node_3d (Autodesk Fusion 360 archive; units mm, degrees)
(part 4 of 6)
derived_instance "DerivedInstance2"
derived_instance "DerivedInstance3"
derived_instance "DerivedInstance4"
derived_instance "DerivedInstance5"
derived_instance "DerivedInstance6"
derived_instance "DerivedInstance7"
derived_instance "DerivedInstance8"
derived_instance "DerivedInstance9"
derived_instance "DerivedInstance10"
derived_instance "DerivedInstance11"
derived_instance "DerivedInstance12"
derived_instance "DerivedInstance1"
derived_instance "DerivedInstance1"
derived_instance "DerivedInstance2"
derived_instance "DerivedInstance3"
derived_instance "DerivedInstance4"
component_insert "Component Insert"
sketch "base" plane through (0, 0, 0) normal (0, 0, 1) x axis (1, 0, 0)
  line L1 (-159.967, -29.782) -> (-254.967, -29.718)
  line L2 (-156.0303, -123.7846) -> (-155.9697, -33.7847)
  line L3 (-255.033, -127.718) -> (-160.033, -127.782)
  line L4 (-258.9697, -33.7154) -> (-259.0303, -123.7153)
  line L5 (-259, -78.7153) -> (-156, -78.7847)
  line L6 (-207.533, -127.75) -> (-207.467, -29.75)
  line L7 (-255, -25.25) -> (-160, -25.25)
  line L8 (-261, -126.25) -> (-261, -31.25)
  line L9 (-160, -132.25) -> (-255, -132.25)
  line L10 (-154, -31.25) -> (-154, -126.25)
  line L11 (-261, -132.25) -> (-154, -25.25)
  line L12 (-154, -132.25) -> (-261, -25.25)
  line L13 (-159.9667, -29.282) -> (-254.9667, -29.218)
  line L14 (-259.4697, -33.715) -> (-259.5303, -123.715)
  line L15 (-255.0333, -128.218) -> (-160.0333, -128.282)
  line L16 (-155.5303, -123.785) -> (-155.4697, -33.785)
  line L17 (-255, -27.25) -> (-160, -27.25)
  line L18 (-259, -126.25) -> (-259, -31.25)
  line L19 (-160, -130.25) -> (-255, -130.25)
  line L20 (-156, -31.25) -> (-156, -126.25)
  arc A1 centre (-254.9697, -33.718) radius 4 clockwise from (-258.9697, -33.7154) to (-254.967, -29.718)
  arc A2 centre (-159.9697, -33.782) radius 4 clockwise from (-159.967, -29.782) to (-155.9697, -33.7847)
  arc A3 centre (-160.0303, -123.782) radius 4 clockwise from (-156.0303, -123.7846) to (-160.033, -127.782)
  arc A4 centre (-255.0303, -123.718) radius 4 clockwise from (-255.033, -127.718) to (-259.0303, -123.7153)
  arc A5 centre (-159.9697, -33.782) radius 4.5 clockwise from (-159.9667, -29.282) to (-155.4697, -33.785)
  arc A6 centre (-254.9697, -33.718) radius 4.5 clockwise from (-259.4697, -33.715) to (-254.9667, -29.218)
  arc A7 centre (-255.0303, -123.718) radius 4.5 clockwise from (-255.0333, -128.218) to (-259.5303, -123.715)
  arc A8 centre (-160.0303, -123.782) radius 4.5 clockwise from (-155.5303, -123.785) to (-160.0333, -128.282)
  arc A9 centre (-255, -126.25) radius 6 clockwise from (-255, -132.25) to (-261, -126.25)
  arc A10 centre (-160, -126.25) radius 6 clockwise from (-154, -126.25) to (-160, -132.25)
  arc A11 centre (-160, -31.25) radius 6 clockwise from (-160, -25.25) to (-154, -31.25)
  arc A12 centre (-255, -31.25) radius 6 clockwise from (-261, -31.25) to (-255, -25.25)
  arc A13 centre (-255, -31.25) radius 4 clockwise from (-259, -31.25) to (-255, -27.25)
  arc A14 centre (-255, -126.25) radius 4 clockwise from (-255, -130.25) to (-259, -126.25)
  arc A15 centre (-160, -126.25) radius 4 clockwise from (-156, -126.25) to (-160, -130.25)
  arc A16 centre (-160, -31.25) radius 4 clockwise from (-160, -27.25) to (-156, -31.25)
  point P2 (-258.967, -29.7154)
  point P3 (-155.967, -29.7847)
  point P4 (-259.033, -127.7153)
  point P17 (-156, -78.7847)
  point P18 (-259, -78.7153)
  point P19 (-207.467, -29.75)
  point P20 (-207.533, -127.75)
  point P25 (-207.5, -78.75)
  point P23 (-261, -132.25)
  point P24 (-154, -132.25)
  point P21 (-154, -25.25)
  point P22 (-261, -25.25)
  coincident P2 L1
  coincident P2 L4
  tangent L1 A1
  tangent L4 A1
  coincident P3 L2
  coincident P3 L1
  tangent L2 A2
  tangent L1 A2
  equal A1 A2
  tangent L3 A3
  tangent L2 A3
  equal A1 A3
  coincident P4 L3
  coincident P4 L4
  tangent L3 A4
  tangent L4 A4
  equal A1 A4
  midpoint L2 P17
  midpoint L4 P18
  midpoint L1 P19
  midpoint L3 P20
  perpendicular L3 L6
  horizontal L7
  perpendicular L7 L8
  parallel L7 L9
  parallel L8 L10
  coincident L11 P25
  coincident L12 P25
  midpoint L6 P25
  coincident P23 L9
  coincident P23 L8
  tangent L9 A9
  tangent L8 A9
  coincident P24 L9
  coincident P24 L10
  tangent L9 A10
  tangent L10 A10
  equal A9 A10
  coincident P21 L10
  coincident P21 L7
  tangent L10 A11
  tangent L7 A11
  equal A9 A11
  coincident P22 L7
  coincident P22 L8
  tangent L7 A12
  tangent L8 A12
  equal A9 A12
  dimension "d3" radius A1 = 4
  dimension "d4" distance L1 L3 = 98
  dimension "d5" distance L2 L4 = 103
  dimension "d6" distance P23 P24 = 107
  dimension "d7" distance P22 P23 = 107
  dimension "d8_1" = -0.5
  dimension "d9_1" = -2
  dimension "d15" radius A9 = 6
extrude "Extrude1" new body sketch "base" profile of L1 L2 L3 L4 A1 A2 A3 A4 L5 L6 L7 L8 L9 L10 L13 L16 A8 L14 A5 A7 L15 A6 L20 L17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 against normal blind 25
shell "Shell1" innerThickness 2
fillet "Fillet1" radius 5
sketch "Sketch5" plane through (0, 0, 0) normal (0, 0, 1) x axis (1, 0, 0)
  line L1 (-240.7563, -46.258) -> (-242.2295, -46.258)
  line L2 (-240.7563, -45.242) -> (-240.7563, -46.258)
  line L3 (-242.2295, -45.242) -> (-240.7563, -45.242)
  line L4 (-242.2295, -44.3328) -> (-242.2295, -45.242)
  line L5 (-242.6105, -44.3328) -> (-242.2295, -44.3328)
  line L6 (-242.6105, -45.242) -> (-242.6105, -44.3328)
  line L7 (-244.0837, -45.242) -> (-242.6105, -45.242)
  line L8 (-244.0837, -46.258) -> (-244.0837, -45.242)
  line L9 (-242.6105, -46.258) -> (-244.0837, -46.258)
  line L10 (-242.6105, -47.1672) -> (-242.6105, -46.258)
  line L11 (-242.2295, -47.1672) -> (-242.6105, -47.1672)
  line L12 (-242.2295, -46.258) -> (-242.2295, -47.1672)
  line L13 (-241, -45.75) -> (-240.7563, -45.75)
  line L14 (-244.0837, -45.75) -> (-241, -45.75)
  line L15 (-242.42, -47.1672) -> (-242.42, -44.3328)
  line L16 (-34.62, 33.38) -> (-34.62, 31.88)
  line L17 (-33.38, 31.88) -> (-34.62, 31.88)
  line L18 (-33.38, 31.9) -> (-33.38, 31.88)
  line L19 (-33.38, 33.38) -> (-33.38, 31.9)
  line L20 (-33.38, 33.38) -> (-31.88, 33.38)
  line L21 (-31.88, 33.38) -> (-31.88, 34.62)
  line L22 (-33.38, 34.62) -> (-31.88, 34.62)
  line L23 (-33.38, 34.62) -> (-33.38, 36.12)
  line L24 (-33.38, 36.12) -> (-34.62, 36.12)
  line L25 (-34.62, 34.62) -> (-34.62, 36.12)
  line L26 (-34.62, 34.62) -> (-36.12, 34.62)
  line L27 (-36.12, 33.38) -> (-36.12, 34.62)
  line L28 (-34.62, 33.38) -> (-36.12, 33.38)
  line L29 (-243.04, -46.37) -> (-243.04, -47.75)
  line L30 (-241.8, -47.75) -> (-243.04, -47.75)
  line L31 (-241.8, -47.85) -> (-241.8, -47.75)
  line L32 (-241.8, -46.37) -> (-241.8, -47.85)
  line L33 (-241.8, -46.37) -> (-240.3, -46.37)
  line L34 (-240.3, -46.37) -> (-240.3, -45.13)
  line L35 (-241.8, -45.13) -> (-240.3, -45.13)
  line L36 (-241.8, -45.13) -> (-241.8, -43.75)
  line L37 (-241.8, -43.75) -> (-243.04, -43.75)
  line L38 (-243.04, -45.13) -> (-243.04, -43.75)
  line L39 (-243.04, -45.13) -> (-244.54, -45.13)
  line L40 (-244.54, -46.37) -> (-244.54, -45.13)
  line L41 (-243.04, -46.37) -> (-244.54, -46.37)
  circle C1 centre (-34, 34) radius 2.75
  circle C2 centre (-242.42, -45.75) radius 2.75
  point P14 (-240.7563, -45.75)
  point P16 (-244.0837, -45.75)
  point P17 (-242.42, -44.3328)
  point P18 (-242.42, -47.1672)
  point P33 (-242.42, -45.75)
  point P29 (-33.38, 36.12)
  point P31 (-34.62, 36.12)
  point P22 (-36.12, 34.62)
  point P24 (-36.12, 33.38)
  point P44 (-241.8, -43.75)
  point P46 (-243.04, -43.75)
  point P37 (-244.54, -45.13)
  point P39 (-244.54, -46.37)
  point P42 (-242.42, -45.75)
  midpoint L2 P14
  perpendicular L2 L13
  midpoint L8 P16
  midpoint L5 P17
  midpoint L11 P18
  horizontal L24
  vertical L27
  perpendicular L26 L27
  perpendicular L27 L28
  perpendicular L16 L28
  perpendicular L20 L21
  perpendicular L25 L26
  perpendicular L22 L23
  perpendicular L17 L18
  perpendicular L17 L19
  midpoint L15 P33
  horizontal L37
  vertical L40
  perpendicular L39 L40
  perpendicular L40 L41
  perpendicular L29 L41
  perpendicular L33 L34
  perpendicular L38 L39
  perpendicular L35 L36
  perpendicular L30 L31
  perpendicular L30 L32
  dimension "d16_1" distance P29 P31 = 1.24
  dimension "d17_1" distance P22 P24 = 1.24
  dimension "d18_1" diameter C1 = 5.5
  dimension "d19_1" distance P44 P46 = 1.24
  dimension "d20_1" distance P37 P39 = 1.24
  dimension "d21_1" diameter C2 = 5.5
  dimension "d22_1" distance P42 L37 = 2
  dimension "d23_1" distance P42 L30 = 2
  dimension "d24_1" distance P42 L40 = 2.12
  dimension "d25_1" distance P33 L34 = 2.12
sketch "flat" plane through (0, 0, 0) normal (0, 0, 1) x axis (1, 0, 0)
  line L1 (-159.5, -30.25) -> (-254.5, -30.25)
  line L2 (-254.5, -128.25) -> (-159.5, -128.25)
  line L3 (-207, -128.25) -> (-207, -30.25)
  line L4 (-155.5, -79.25) -> (-258.5, -79.25)
  line L5 (-258.5, -27.75) -> (-155.5, -130.75)
  line L6 (-155.5, -27.75) -> (-258.5, -130.75)
  line L7 (-250.4, -129.15) -> (-163.6, -129.15)
  line L8 (-256.9, -35.85) -> (-256.9, -122.65)
  line L9 (-163.6, -29.35) -> (-250.4, -29.35)
  line L10 (-157.1, -122.65) -> (-157.1, -35.85)
  line L11 (-192, -27.75) -> (-222, -27.75)
  line L12 (-196.59, -130.75) -> (-163.6, -130.75)
  line L13 (-155.5, -122.65) -> (-155.5, -35.85)
  line L14 (-163.6, -27.75) -> (-250.4, -27.75)
  line L15 (-258.5, -35.85) -> (-258.5, -122.65)
  line L16 (-217, -130.75) -> (-197, -130.75)
  line L17 (-217, -129.15) -> (-217, -130.34)
  line L18 (-197, -129.15) -> (-217, -129.15)
  line L19 (-197, -130.34) -> (-197, -129.15)
  line L20 (-217.41, -130.75) -> (-250.4, -130.75)
  line L21 (-155.5, -89.25) -> (-155.5, -69.25)
  line L22 (-155.91, -69.25) -> (-157.1, -69.25)
  line L23 (-157.1, -69.25) -> (-157.1, -89.25)
  line L24 (-157.1, -89.25) -> (-155.91, -89.25)
  line L25 (-197, -27.75) -> (-217, -27.75)
  line L26 (-217, -28.16) -> (-217, -29.35)
  line L27 (-217, -29.35) -> (-197, -29.35)
  line L28 (-197, -29.35) -> (-197, -28.16)
  line L29 (-258.5, -69.25) -> (-258.5, -89.25)
  line L30 (-258.09, -89.25) -> (-256.9, -89.25)
  line L31 (-256.9, -89.25) -> (-256.9, -69.25)
  line L32 (-256.9, -69.25) -> (-258.09, -69.25)
  line L33 (-217.41, -130.75) -> (-196.59, -130.75)
  arc A1 centre (-254.5, -34.25) radius 4 clockwise from (-258.5, -34.25) to (-254.5, -30.25)
  arc A2 centre (-159.5, -34.25) radius 4 clockwise from (-159.5, -30.25) to (-155.5, -34.25)
  arc A3 centre (-159.5, -124.25) radius 4 clockwise from (-155.5, -124.25) to (-159.5, -128.25)
  arc A4 centre (-254.5, -124.25) radius 4 clockwise from (-254.5, -128.25) to (-258.5, -124.25)
  arc A5 centre (-163.6, -122.65) radius 6.5 clockwise from (-157.1, -122.65) to (-163.6, -129.15)
  arc A6 centre (-250.4, -122.65) radius 6.5 clockwise from (-250.4, -129.15) to (-256.9, -122.65)
  arc A7 centre (-250.4, -35.85) radius 6.5 clockwise from (-256.9, -35.85) to (-250.4, -29.35)
  arc A8 centre (-163.6, -35.85) radius 6.5 clockwise from (-163.6, -29.35) to (-157.1, -35.85)
  arc A9 centre (-250.4, -122.65) radius 8.1 clockwise from (-250.4, -130.75) to (-258.5, -122.65)
  arc A10 centre (-163.6, -122.65) radius 8.1 clockwise from (-155.5, -122.65) to (-163.6, -130.75)
  arc A11 centre (-163.6, -35.85) radius 8.1 clockwise from (-163.6, -27.75) to (-155.5, -35.85)
  arc A12 centre (-250.4, -35.85) radius 8.1 clockwise from (-258.5, -35.85) to (-250.4, -27.75)
  arc A13 centre (-196.59, -130.34) radius 0.41 clockwise from (-196.59, -130.75) to (-197, -130.34)
  arc A14 centre (-217.41, -130.34) radius 0.41 clockwise from (-217, -130.34) to (-217.41, -130.75)
  arc A15 centre (-155.91, -68.84) radius 0.41 clockwise from (-155.5, -68.84) to (-155.91, -69.25)
  arc A16 centre (-155.91, -89.66) radius 0.41 clockwise from (-155.91, -89.25) to (-155.5, -89.66)
  arc A17 centre (-217.41, -28.16) radius 0.41 clockwise from (-217.41, -27.75) to (-217, -28.16)
  arc A18 centre (-196.59, -28.16) radius 0.41 clockwise from (-197, -28.16) to (-196.59, -27.75)
  arc A19 centre (-258.09, -89.66) radius 0.41 clockwise from (-258.5, -89.66) to (-258.09, -89.25)
  arc A20 centre (-258.09, -68.84) radius 0.41 clockwise from (-258.09, -69.25) to (-258.5, -68.84)
  point P13 (-207, -79.25)
  point P5 (-207, -30.25)
  point P2 (-258.5, -30.25)
  point P3 (-155.5, -30.25)
  point P6 (-207, -128.25)
  point P4 (-258.5, -128.25)
  point P52 (-197, -130.75)
  point P53 (-217, -130.75)
  point P11 (-258.5, -27.75)
  point P12 (-155.5, -27.75)
  point P10 (-258.5, -130.75)
  point P26 (-222, -27.75)
  point P27 (-192, -27.75)
  point P55 (-197, -129.15)
  coincident L5 P13
  coincident L6 P13
  midpoint L4 P13
  coincident L1 P5
  coincident P2 L1
  tangent L1 A1
  coincident P3 L1
  tangent L1 A2
  coincident L2 P6
  tangent L2 A3
  equal A2 A3
  coincident P4 L2
  tangent L2 A4
  equal A2 A4
  horizontal L11
  tangent L7 A5
  tangent L10 A5
  tangent L7 A6
  tangent L8 A6
  tangent L8 A7
  tangent L9 A7
  equal A6 A7
  tangent L9 A8
  tangent L10 A8
  equal A6 A8
  horizontal L16
  vertical L17
  horizontal L18
  vertical L19
  concentric A6 A9
  concentric A5 A10
  concentric A8 A11
  concentric A7 A12
  tangent A9 L15
  tangent L14 A12
  tangent L13 A11
  tangent A9 L12
  tangent A10 L13
  tangent L12 A10
  tangent A11 L14
  tangent A12 L15
  coincident L12 L16
  coincident P52 L19
  tangent L12 A13
  tangent L19 A13
  tangent A9 L20
  coincident P53 L20
  coincident P53 L17
  tangent L20 A14
  tangent L17 A14
  dimension "d26_1" distance P2 P3 = 103
  dimension "d27_1" distance P2 P4 = 98
  dimension "d28_1" distance P11 P12 = 103
  dimension "d29_1" distance P10 P11 = 103
  dimension "d30_1" radius A1 = 4
  dimension "d31" radius A2 = 4
  dimension "d35_1" distance P26 P27 = 30
  dimension "d47" radius A5 = 6.5
  dimension "d48" radius A6 = 6.5
  dimension "d59" distance P52 P53 = 20
  dimension "d60" distance P52 P55 = 1.6
  dimension "d61" radius A13 = 0.41
  dimension "d62" radius A14 = 0.41
  dimension "d64" C-Pattern1-Angle = 360
extrude "Extrude2" new body sketch "flat" profile of L7 L10 L9 L8 A5 A6 A7 A8 along normal blind 1.6
sketch "perp" plane through (0, 0, 0) normal (0, 1, 0) x axis (1, 0, 0)
  line L1 (-196.59, 0) -> (-163.6, 0)
  line L2 (-196.59, -1.6) -> (-196.59, 0)
  line L3 (-163.6, -1.6) -> (-196.59, -1.6)
  line L4 (-163.6, 0) -> (-163.6, -1.6)
  line L5 (-196.59, 0) -> (-197, 0)
  line L6 (-197, -1.6) -> (-197, 0)
  line L7 (-196.59, -1.6) -> (-197, -1.6)
  line L8 (-196.59, 0) -> (-196.59, -1.6)
  line L9 (-217, 0) -> (-197, 0)
  line L10 (-217, -1.6) -> (-217, 0)
  line L11 (-197, -1.6) -> (-217, -1.6)
  line L12 (-197, 0) -> (-197, -1.6)
  line L13 (-250.4, 0) -> (-217.41, 0)
  line L14 (-250.4, -1.6) -> (-250.4, 0)
  line L15 (-217.41, -1.6) -> (-250.4, -1.6)
  line L16 (-217.41, 0) -> (-217.41, -1.6)
  line L17 (-217, 0) -> (-217.41, 0)
  line L18 (-217.41, -1.6) -> (-217.41, 0)
  line L19 (-217, -1.6) -> (-217.41, -1.6)
  line L20 (-217, 0) -> (-217, -1.6)
  line L21 (-207, 0) -> (-207, -1.6)
  line L22 (-217, -0.8) -> (-197, -0.8)
  line L23 (-196, 4.2) -> (-218, 4.2)
  line L24 (-193, -2.8) -> (-193, 1.2)
  line L25 (-218, -5.8) -> (-196, -5.8)
  line L26 (-221, 1.2) -> (-221, -2.8)
  line L27 (-193, -5.8) -> (-221, 4.2)
  line L28 (-221, -5.8) -> (-193, 4.2)
  line L29 (-217, -1.6) -> (-221, -1.6)
  line L30 (-217, 0) -> (-217, -1.6)
  line L31 (-221, 0) -> (-217, 0)
  line L32 (-221, -1.6) -> (-221, 0)
  line L33 (-221.2, 0.2) -> (-216.8, 0.2)
  line L34 (-221.2, -1.8) -> (-221.2, 0.2)
  line L35 (-216.8, -1.8) -> (-221.2, -1.8)
  line L36 (-216.8, 0.2) -> (-216.8, -1.8)
  line L37 (-197.2, -1.8) -> (-192.8, -1.8)
  line L38 (-197.2, 0.2) -> (-197.2, -1.8)
  line L39 (-192.8, -1.8) -> (-192.8, 0.2)
  line L40 (-192.8, 0.2) -> (-197.2, 0.2)
  line L41 (-207.85, -3.24) -> (-207.85, 1.64)
  line L42 (-206.15, 1.64) -> (-206.15, -3.24)
  line L43 (-207.85, -4.09) -> (-206.15, 2.49)
  line L44 (-206.15, -4.09) -> (-207.85, 2.49)
  line L45 (-208.69, 1.64) -> (-208.69, -3.24)
  line L46 (-210.39, -3.24) -> (-210.39, 1.64)
  line L47 (-211.23, 1.64) -> (-211.23, -3.24)
  line L48 (-212.93, -3.24) -> (-212.93, 1.64)
  line L49 (-203.61, 1.64) -> (-203.61, -3.24)
  line L50 (-205.31, -3.24) -> (-205.31, 1.64)
  line L51 (-201.07, 1.64) -> (-201.07, -3.24)
  line L52 (-202.77, -3.24) -> (-202.77, 1.64)
  arc A1 centre (-196, -2.8) radius 3 clockwise from (-193, -2.8) to (-196, -5.8)
  arc A2 centre (-196, 1.2) radius 3 clockwise from (-196, 4.2) to (-193, 1.2)
  arc A3 centre (-218, 1.2) radius 3 clockwise from (-221, 1.2) to (-218, 4.2)
  arc A4 centre (-218, -2.8) radius 3 clockwise from (-218, -5.8) to (-221, -2.8)
  arc A5 centre (-207, -3.24) radius 0.85 clockwise from (-207, -4.09) to (-207.85, -3.24)
  arc A6 centre (-207, -3.24) radius 0.85 clockwise from (-206.15, -3.24) to (-207, -4.09)
  arc A7 centre (-207, 1.64) radius 0.85 clockwise from (-207.85, 1.64) to (-207, 2.49)
  arc A8 centre (-207, 1.64) radius 0.85 clockwise from (-207, 2.49) to (-206.15, 1.64)
  arc A9 centre (-209.54, -3.24) radius 0.85 clockwise from (-208.69, -3.24) to (-209.54, -4.09)
  arc A10 centre (-209.54, 1.64) radius 0.85 clockwise from (-209.54, 2.49) to (-208.69, 1.64)
  arc A11 centre (-209.54, -3.24) radius 0.85 clockwise from (-209.54, -4.09) to (-210.39, -3.24)
  arc A12 centre (-209.54, 1.64) radius 0.85 clockwise from (-210.39, 1.64) to (-209.54, 2.49)
  arc A13 centre (-212.08, -3.24) radius 0.85 clockwise from (-211.23, -3.24) to (-212.08, -4.09)
  arc A14 centre (-212.08, 1.64) radius 0.85 clockwise from (-212.08, 2.49) to (-211.23, 1.64)
  arc A15 centre (-212.08, -3.24) radius 0.85 clockwise from (-212.08, -4.09) to (-212.93, -3.24)
  arc A16 centre (-212.08, 1.64) radius 0.85 clockwise from (-212.93, 1.64) to (-212.08, 2.49)
  arc A17 centre (-204.46, -3.24) radius 0.85 clockwise from (-203.61, -3.24) to (-204.46, -4.09)
  arc A18 centre (-204.46, 1.64) radius 0.85 clockwise from (-204.46, 2.49) to (-203.61, 1.64)
  arc A19 centre (-204.46, -3.24) radius 0.85 clockwise from (-204.46, -4.09) to (-205.31, -3.24)
  arc A20 centre (-204.46, 1.64) radius 0.85 clockwise from (-205.31, 1.64) to (-204.46, 2.49)
  arc A21 centre (-201.92, -3.24) radius 0.85 clockwise from (-201.07, -3.24) to (-201.92, -4.09)
  arc A22 centre (-201.92, 1.64) radius 0.85 clockwise from (-201.92, 2.49) to (-201.07, 1.64)
  arc A23 centre (-201.92, -3.24) radius 0.85 clockwise from (-201.92, -4.09) to (-202.77, -3.24)
  arc A24 centre (-201.92, 1.64) radius 0.85 clockwise from (-202.77, 1.64) to (-201.92, 2.49)
  circle C1 centre (-207, -0.8) radius 0.5
  circle C2 centre (-204.46, -0.8) radius 0.5
  circle C3 centre (-201.92, -0.8) radius 0.5
  circle C4 centre (-209.54, -0.8) radius 0.5
  circle C5 centre (-212.08, -0.8) radius 0.5
  point P22 (-207, -1.6)
  point P23 (-207, 0)
  point P24 (-197, -0.8)
  point P25 (-217, -0.8)
  point P30 (-207, -0.8)
  point P11 (-217, 0)
  point P33 (-217, 0)
  point P31 (-221, -1.6)
  point P35 (-216.8, 0.2)
  point P41 (-197.2, 0.2)
  point P36 (-221.2, 0.2)
  point P42 (-192.8, 0.2)
  point P37 (-221.2, -1.8)
  point P39 (-192.8, -1.8)
  point P38 (-216.8, -1.8)
  point P40 (-197.2, -1.8)
  point P28 (-193, -5.8)
  point P27 (-193, 4.2)
  point P26 (-221, 4.2)
  point P29 (-221, -5.8)
  point P59 (-207, -0.8)
  point P57 (-207.85, -4.09)
  point P58 (-206.15, -4.09)
  point P60 (-207, -4.09)
  point P63 (-207, -4.09)
  point P56 (-207.85, 2.49)
  point P55 (-206.15, 2.49)
  point P67 (-207, 2.49)
  point P70 (-207, 2.49)
  point P120 (-207, -0.8)
  midpoint L11 P22
  midpoint L9 P23
  midpoint L12 P24
  midpoint L20 P25
  horizontal L23
  perpendicular L23 L24
  parallel L23 L25
  parallel L24 L26
  coincident L27 P30
  coincident L28 P30
  midpoint L22 P30
  horizontal L29
  vertical L30
  horizontal L31
  vertical L32
  coincident P11 P33
  coincident L26 P31
  coincident L15 P31
  symmetric L21 P35 P41
  symmetric L21 P36 P42
  symmetric L21 P37 P39
  symmetric L21 P38 P40
  coincident P28 L25
  coincident P28 L24
  tangent L25 A1
  tangent L24 A1
  coincident P27 L24
  coincident P27 L23
  tangent L24 A2
  tangent L23 A2
  equal A1 A2
  coincident P26 L23
  coincident P26 L26
  tangent L23 A3
  tangent L26 A3
  equal A1 A3
  coincident P29 L26
  coincident P29 L25
  tangent L26 A4
  tangent L25 A4
  equal A1 A4
  parallel L41 L42
  coincident L43 P59
  coincident L44 P59
  coincident P30 P59
  coincident P57 L41
  tangent L41 A5
  coincident P58 L42
  tangent L42 A6
  coincident P60 P63
  coincident P56 L41
  tangent L41 A7
  equal A6 A7
  coincident P55 L42
  tangent L42 A8
  equal A6 A8
  coincident P67 P70
  coincident P59 P120
  dimension "d65" distance P28 P29 = 28
  dimension "d66" distance P27 P28 = 10
  dimension "d67" = 0.2
  dimension "d71" radius A1 = 3
  dimension "d92" distance P57 P58 = 1.7
  dimension "d93" distance P56 P57 = 6.58
  dimension "d94" radius A5 = 0.85
  dimension "d95" radius A6 = 0.85
  dimension "d109" diameter C1 = 1
  dimension "d98" R-Pattern1-uDistance = -2.54
  dimension "d99" R-Pattern1-vDistance = 0
  dimension "d102" R-Pattern2-uDistance = 2.54
  dimension "d103" R-Pattern2-vDistance = 0
  dimension "d112" R-Pattern3-uDistance = 2.54
  dimension "d113" R-Pattern3-vDistance = 0
  dimension "d116" R-Pattern4-uDistance = -2.54
  dimension "d117" R-Pattern4-vDistance = 0
extrude "Extrude3" sketch "perp" profile of L9 L11 L23 L24 L25 L26 L36 L33 L35 L37 L38 L40 A1 A2 A3 A4 L41 L42 A5 A6 A7 A8 A9 L45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 blind 1.6
extrude "Extrude4" sketch "perp" profile of L9 L11 L23 L24 L25 L26 L36 L33 L35 L37 L38 L40 A1 A2 A3 A4 L41 L42 A5 A6 A7 A8 A9 L45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 blind -1.6
component_from_bodies "Body->Comp1"
component_from_bodies "Body->Comp2"
sketch "body" plane through (0, 0, 0) normal (0, 0, 1) x axis (1, 0, 0)
  line L1 (-157.1, -69.25) -> (-157.1, -89.25)
  line L2 (-155.91, -69.25) -> (-157.1, -69.25)
  line L3 (-155.5, -35.85) -> (-155.5, -68.84)
  line L4 (-196.59, -27.75) -> (-163.6, -27.75)
  line L5 (-197, -29.35) -> (-197, -28.16)
  line L6 (-217, -29.35) -> (-197, -29.35)
  line L7 (-217, -28.16) -> (-217, -29.35)
  line L8 (-250.4, -27.75) -> (-217.41, -27.75)
  line L9 (-258.5, -68.84) -> (-258.5, -35.85)
  line L10 (-256.9, -69.25) -> (-258.09, -69.25)
  line L11 (-256.9, -89.25) -> (-256.9, -69.25)
  line L12 (-258.09, -89.25) -> (-256.9, -89.25)
  line L13 (-258.5, -122.65) -> (-258.5, -89.66)
  line L14 (-217.41, -130.75) -> (-250.4, -130.75)
  line L15 (-217, -129.15) -> (-217, -130.34)
  line L16 (-197, -129.15) -> (-217, -129.15)
  line L17 (-197, -130.34) -> (-197, -129.15)
  line L18 (-163.6, -130.75) -> (-196.59, -130.75)
  line L19 (-155.5, -89.66) -> (-155.5, -122.65)
  line L20 (-157.1, -89.25) -> (-155.91, -89.25)
  line L21 (-256.9, -68.25) -> (-256.9, -90.25)
  line L22 (-258.5, -68.25) -> (-256.9, -68.25)
  line L23 (-258.5, -90.25) -> (-258.5, -68.25)
  line L24 (-256.9, -90.25) -> (-258.5, -90.25)
  line L25 (-196, -29.35) -> (-218, -29.35)
  line L26 (-196, -27.75) -> (-196, -29.35)
  line L27 (-218, -27.75) -> (-196, -27.75)
  line L28 (-218, -29.35) -> (-218, -27.75)
  line L29 (-155.5, -68.25) -> (-155.5, -90.25)
  line L30 (-157.1, -68.25) -> (-155.5, -68.25)
  line L31 (-157.1, -90.25) -> (-157.1, -68.25)
  line L32 (-155.5, -90.25) -> (-157.1, -90.25)
  line L33 (-218, -129.15) -> (-196, -129.15)
  line L34 (-218, -130.75) -> (-218, -129.15)
  line L35 (-196, -130.75) -> (-218, -130.75)
  line L36 (-196, -129.15) -> (-196, -130.75)
  line L37 (-207, -129.15) -> (-207, -29.35)
  line L38 (-256.9, -79.25) -> (-157.1, -79.25)
  line L39 (-250.4, -26.75) -> (-163.6, -26.75)
  line L40 (-259.5, -122.65) -> (-259.5, -35.85)
  line L41 (-163.6, -131.75) -> (-250.4, -131.75)
  line L42 (-154.5, -35.85) -> (-154.5, -122.65)
  line L43 (-259.5, -131.75) -> (-154.5, -26.75)
  line L44 (-154.5, -131.75) -> (-259.5, -26.75)
  line L45 (-260.5, -122.65) -> (-260.5, -35.85)
  line L46 (-163.6, -132.75) -> (-250.4, -132.75)
  line L47 (-153.5, -35.85) -> (-153.5, -122.65)
  line L48 (-250.4, -25.75) -> (-163.6, -25.75)
  line L49 (-163.6, -131.15) -> (-250.4, -131.15)
  line L50 (-155.1, -35.85) -> (-155.1, -122.65)
  line L51 (-250.4, -27.35) -> (-163.6, -27.35)
  line L52 (-258.9, -122.65) -> (-258.9, -35.85)
  arc A1 centre (-155.91, -68.84) radius 0.41 clockwise from (-155.5, -68.84) to (-155.91, -69.25)
  arc A2 centre (-163.6, -35.85) radius 8.1 clockwise from (-163.6, -27.75) to (-155.5, -35.85)
  arc A3 centre (-196.59, -28.16) radius 0.41 clockwise from (-197, -28.16) to (-196.59, -27.75)
  arc A4 centre (-217.41, -28.16) radius 0.41 clockwise from (-217.41, -27.75) to (-217, -28.16)
  arc A5 centre (-250.4, -35.85) radius 8.1 clockwise from (-258.5, -35.85) to (-250.4, -27.75)
  arc A6 centre (-258.09, -68.84) radius 0.41 clockwise from (-258.09, -69.25) to (-258.5, -68.84)
  arc A7 centre (-258.09, -89.66) radius 0.41 clockwise from (-258.5, -89.66) to (-258.09, -89.25)
  arc A8 centre (-250.4, -122.65) radius 8.1 clockwise from (-250.4, -130.75) to (-258.5, -122.65)
  arc A9 centre (-217.41, -130.34) radius 0.41 clockwise from (-217, -130.34) to (-217.41, -130.75)
  arc A10 centre (-196.59, -130.34) radius 0.41 clockwise from (-196.59, -130.75) to (-197, -130.34)
  arc A11 centre (-163.6, -122.65) radius 8.1 clockwise from (-155.5, -122.65) to (-163.6, -130.75)
  arc A12 centre (-155.91, -89.66) radius 0.41 clockwise from (-155.91, -89.25) to (-155.5, -89.66)
  arc A13 centre (-163.6, -122.65) radius 9.1 clockwise from (-154.5, -122.65) to (-163.6, -131.75)
  arc A14 centre (-250.4, -122.65) radius 9.1 clockwise from (-250.4, -131.75) to (-259.5, -122.65)
  arc A15 centre (-250.4, -35.85) radius 9.1 clockwise from (-259.5, -35.85) to (-250.4, -26.75)
  arc A16 centre (-163.6, -35.85) radius 9.1 clockwise from (-163.6, -26.75) to (-154.5, -35.85)
  arc A17 centre (-250.4, -122.65) radius 10.1 clockwise from (-250.4, -132.75) to (-260.5, -122.65)
  arc A18 centre (-163.6, -122.65) radius 10.1 clockwise from (-153.5, -122.65) to (-163.6, -132.75)
  arc A19 centre (-163.6, -35.85) radius 10.1 clockwise from (-163.6, -25.75) to (-153.5, -35.85)
  arc A20 centre (-250.4, -35.85) radius 10.1 clockwise from (-260.5, -35.85) to (-250.4, -25.75)
  arc A21 centre (-250.4, -122.65) radius 8.5 clockwise from (-250.4, -131.15) to (-258.9, -122.65)
  arc A22 centre (-163.6, -122.65) radius 8.5 clockwise from (-155.1, -122.65) to (-163.6, -131.15)
  arc A23 centre (-163.6, -35.85) radius 8.5 clockwise from (-163.6, -27.35) to (-155.1, -35.85)
  arc A24 centre (-250.4, -35.85) radius 8.5 clockwise from (-258.9, -35.85) to (-250.4, -27.35)
  point P62 (-207, -29.35)
  point P63 (-207, -129.15)
  point P64 (-157.1, -79.25)
  point P65 (-256.9, -79.25)
  point P70 (-207, -79.25)
  point P69 (-154.5, -131.75)
  point P68 (-259.5, -131.75)
  point P67 (-259.5, -26.75)
  point P66 (-154.5, -26.75)
  midpoint L25 P62
  midpoint L16 P63
  perpendicular L16 L37
  midpoint L31 P64
  midpoint L11 P65
  horizontal L39
  perpendicular L39 L40
  parallel L39 L41
  parallel L40 L42
  coincident L43 P70
  coincident L44 P70
  midpoint L37 P70
  coincident P69 L42
  coincident P69 L41
  tangent L42 A13
  tangent L41 A13
  coincident P68 L41
  coincident P68 L40
  tangent L41 A14
  tangent L40 A14
  coincident P67 L39
  coincident P67 L40
  tangent L39 A15
  tangent L40 A15
  coincident P66 L39
  coincident P66 L42
  tangent L39 A16
  tangent L42 A16
  equal A15 A16
  dimension "d80" distance P68 P69 = 105
  dimension "d81" distance P67 P68 = 105
  dimension "d82" radius A13 = 9.1
  dimension "d83" radius A14 = 9.1
  dimension "d84" radius A15 = 9.1
  dimension "d172" = 1
  dimension "d173" = -0.6
extrude "Extrude5" new body sketch "body" profile of L1 L2 A1 L3 A2 L4 A3 L5 L6 L7 A4 L8 A5 L9 A6 L10 L11 L12 A7 L13 A8 L14 A9 L15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 along normal blind 15 and against normal blind 10
shell "Shell2" innerThickness 1.5
fillet "Fillet2" radius 5
extrude "Extrude1" sketch "perp" profile of L9 L11 L41 L42 A5 A6 A7 A8 A9 L45 A10 L46 A11 A12 A13 L47 A14 L48 A15 A16 A17 L49 A18 L50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 blind 0.1 second side blind 1.7
position "Position1"
extrude "Extrude2" sketch "perp" profile of C1 C2 C3 C4 C5 blind 4
fillet "Fillet1" radius 0.5
work_plane "WorkPlane1"
work_plane "WorkPlane2" AlongDistance 0
sketch "Sketch10" plane through (0, -26.75, 0) normal (0, 1, 0) x axis (1, 0, 0)
  line L1 (-202.77, -3.24) -> (-202.77, 1.64)
  line L2 (-201.07, 1.64) -> (-201.07, -3.24)
  line L3 (-205.31, -3.24) -> (-205.31, 1.64)
  line L4 (-203.61, 1.64) -> (-203.61, -3.24)
  line L5 (-207.85, -3.24) -> (-207.85, 1.64)
  line L6 (-206.15, 1.64) -> (-206.15, -3.24)
  line L7 (-210.39, -3.24) -> (-210.39, 1.64)
  line L8 (-208.69, 1.64) -> (-208.69, -3.24)
  line L9 (-212.93, -3.24) -> (-212.93, 1.64)
  line L10 (-211.23, 1.64) -> (-211.23, -3.24)
  line L11 (-211.93, -2.3) -> (-202.07, -2.3)
  line L12 (-202.07, 0.7) -> (-211.93, 0.7)
  line L13 (-250.4, 5) -> (-163.6, 5)
  line L14 (-250.4, -15) -> (-250.4, 5)
  line L15 (-163.6, -15) -> (-250.4, -15)
  line L16 (-163.6, 5) -> (-163.6, -15)
  line L17 (-163.6, 10) -> (-163.6, 5)
  line L18 (-250.4, 10) -> (-163.6, 10)
  line L19 (-250.4, 5) -> (-250.4, 10)
  line L20 (-163.6, 5) -> (-250.4, 5)
  line L21 (-250.4, 4.3901) -> (-163.6, 4.3901)
  circle C1 centre (-201.92, -0.8) radius 0.5
  arc A1 centre (-201.92, -3.24) radius 0.85 clockwise from (-201.07, -3.24) to (-202.77, -3.24)
  arc A2 centre (-201.92, 1.64) radius 0.85 clockwise from (-202.77, 1.64) to (-201.07, 1.64)
  circle C2 centre (-204.46, -0.8) radius 0.5
  arc A3 centre (-204.46, -3.24) radius 0.85 clockwise from (-203.61, -3.24) to (-205.31, -3.24)
  arc A4 centre (-204.46, 1.64) radius 0.85 clockwise from (-205.31, 1.64) to (-203.61, 1.64)
  circle C3 centre (-207, -0.8) radius 0.5
  arc A5 centre (-207, -3.24) radius 0.85 clockwise from (-206.15, -3.24) to (-207.85, -3.24)
  arc A6 centre (-207, 1.64) radius 0.85 clockwise from (-207.85, 1.64) to (-206.15, 1.64)
  circle C4 centre (-209.54, -0.8) radius 0.5
  arc A7 centre (-209.54, -3.24) radius 0.85 clockwise from (-208.69, -3.24) to (-210.39, -3.24)
  arc A8 centre (-209.54, 1.64) radius 0.85 clockwise from (-210.39, 1.64) to (-208.69, 1.64)
  circle C5 centre (-212.08, -0.8) radius 0.5
  arc A9 centre (-212.08, -3.24) radius 0.85 clockwise from (-211.23, -3.24) to (-212.93, -3.24)
  arc A10 centre (-212.08, 1.64) radius 0.85 clockwise from (-212.93, 1.64) to (-211.23, 1.64)
  arc A11 centre (-202.07, -0.8) radius 1.5 clockwise from (-200.57, -0.8) to (-202.07, -2.3)
  arc A12 centre (-202.07, -0.8) radius 1.5 clockwise from (-202.07, 0.7) to (-200.57, -0.8)
  arc A13 centre (-211.93, -0.8) radius 1.5 clockwise from (-211.93, -2.3) to (-213.43, -0.8)
  arc A14 centre (-211.93, -0.8) radius 1.5 clockwise from (-213.43, -0.8) to (-211.93, 0.7)
  point P37 (-200.57, -0.8)
  point P41 (-200.57, -0.8)
  point P44 (-213.43, -0.8)
  point P46 (-213.43, -0.8)
  point P57 (-163.6, 4.3901)
  point P58 (-250.4, 4.3901)
  horizontal L11
  horizontal L12
  tangent L11 A11
  tangent L12 A12
  equal A11 A12
  coincident P37 P41
  tangent L11 A13
  tangent L12 A14
  equal A13 A14
  coincident P44 P46
  coincident L16 P57
  coincident L14 P58
  perpendicular L14 L21
  dimension "d134" radius A11 = 1.5
  dimension "d135" radius A13 = 1.5
extrude "Extrude6" cut sketch "Sketch10" profile of C1 L1 L2 C2 L3 L4 C3 L5 L6 C4 L7 L8 C5 L9 L10 L11 L12 A11 A12 A13 A14 distance -120
sketch "Sketch11" plane through (0, 0, 0) normal (0, 0, 1) x axis (1, 0, 0)
  line L1 (-154.5, -122.65) -> (-154.5, -35.85)
  line L2 (-250.4, -131.75) -> (-163.6, -131.75)
  line L3 (-259.5, -35.85) -> (-259.5, -122.65)
  line L4 (-163.6, -26.75) -> (-250.4, -26.75)
  line L5 (-250.4, -130.25) -> (-163.6, -130.25)
  line L6 (-156, -122.65) -> (-156, -35.85)
  line L7 (-250.4, -130.25) -> (-163.6, -130.25)
  line L8 (-258, -35.85) -> (-258, -122.65)
  line L9 (-163.6, -28.25) -> (-250.4, -28.25)
  line L10 (-250.4, -26.75) -> (-163.6, -26.75)
  line L11 (-259.5, -122.65) -> (-259.5, -35.85)
  line L12 (-163.6, -131.75) -> (-250.4, -131.75)
  line L13 (-154.5, -35.85) -> (-154.5, -122.65)
  line L14 (-160, -109.75) -> (-156, -109.75)
  line L15 (-160, -99.75) -> (-160, -109.75)
  line L16 (-156, -99.75) -> (-160, -99.75)
  line L17 (-156, -109.75) -> (-156, -99.75)
  line L18 (-256.31, -79.25) -> (-258, -79.25)
  line L19 (-154.5, -79.25) -> (-256.31, -79.25)
  line L20 (-207, -26.75) -> (-207, -130.25)
  line L21 (-189.0153, -79.25) -> (-189.0153, -130.25)
  line L22 (-156, -104.75) -> (-189.0153, -104.75)
  line L23 (-156, -53.75) -> (-189.0153, -53.75)
  line L24 (-156, -48.75) -> (-156, -58.75)
  line L25 (-160, -48.75) -> (-156, -48.75)
  line L26 (-156, -58.75) -> (-160, -58.75)
  line L27 (-160, -58.75) -> (-160, -48.75)
  line L28 (-159, -122.65) -> (-159, -35.85)
  line L29 (-163.6, -31.25) -> (-250.4, -31.25)
  line L30 (-255, -35.85) -> (-255, -122.65)
  line L31 (-160, -107.55) -> (-156, -109.75)
  line L32 (-160, -101.95) -> (-156, -99.75)
  arc A1 centre (-163.6, -35.85) radius 9.1 clockwise from (-163.6, -26.75) to (-154.5, -35.85)
  arc A2 centre (-163.6, -122.65) radius 9.1 clockwise from (-154.5, -122.65) to (-163.6, -131.75)
  arc A3 centre (-250.4, -122.65) radius 9.1 clockwise from (-250.4, -131.75) to (-259.5, -122.65)
  arc A4 centre (-250.4, -35.85) radius 9.1 clockwise from (-259.5, -35.85) to (-250.4, -26.75)
  arc A5 centre (-250.4, -122.65) radius 7.6 clockwise from (-250.4, -130.25) to (-258, -122.65)
  arc A6 centre (-163.6, -122.65) radius 7.6 clockwise from (-156, -122.65) to (-163.6, -130.25)
  arc A7 centre (-250.4, -122.65) radius 7.6 clockwise from (-250.4, -130.25) to (-258, -122.65)
  arc A8 centre (-250.4, -35.85) radius 7.6 clockwise from (-258, -35.85) to (-250.4, -28.25)
  arc A9 centre (-163.6, -35.85) radius 7.6 clockwise from (-163.6, -28.25) to (-156, -35.85)
  arc A10 centre (-163.6, -35.85) radius 9.1 clockwise from (-163.6, -26.75) to (-154.5, -35.85)
  arc A11 centre (-250.4, -35.85) radius 9.1 clockwise from (-259.5, -35.85) to (-250.4, -26.75)
  arc A12 centre (-250.4, -122.65) radius 9.1 clockwise from (-250.4, -131.75) to (-259.5, -122.65)
  arc A13 centre (-163.6, -122.65) radius 9.1 clockwise from (-154.5, -122.65) to (-163.6, -131.75)
  arc A14 centre (-163.6, -122.65) radius 4.6 clockwise from (-159, -122.65) to (-163.6, -127.25)
  arc A15 centre (-163.6, -35.85) radius 4.6 clockwise from (-163.6, -31.25) to (-159, -35.85)
  arc A16 centre (-250.4, -35.85) radius 4.6 clockwise from (-255, -35.85) to (-250.4, -31.25)
  point P43 (-258, -79.25)
  point P45 (-154.5, -79.25)
  point P46 (-207, -130.25)
  point P47 (-207, -26.75)
  point P48 (-189.0153, -130.25)
  point P49 (-189.0153, -79.25)
  point P50 (-189.0153, -104.75)
  point P51 (-156, -104.75)
  point P52 (-189.0153, -53.75)
  point P53 (-156, -53.75)
  point P39 (-156, -109.75)
  point P55 (-156, -48.75)
  point P40 (-160, -109.75)
  point P56 (-160, -48.75)
  point P41 (-160, -99.75)
  point P57 (-160, -58.75)
  point P42 (-156, -99.75)
  point P54 (-156, -58.75)
  point P68 (-160, -107.55)
  point P69 (-156, -99.75)
  point P70 (-160, -101.95)
  horizontal L14
  vertical L15
  horizontal L16
  vertical L17
  midpoint L8 P43
  perpendicular L8 L18
  midpoint L13 P45
  perpendicular L13 L19
  midpoint L7 P46
  midpoint L10 P47
  coincident L5 P48
  coincident L19 P49
  perpendicular L19 L21
  midpoint L21 P50
  coincident L6 P51
  perpendicular L6 L22
  symmetric L19 P50 P52
  symmetric L19 P51 P53
  midpoint L17 P51
  symmetric P39 L19 P55
  symmetric P40 L19 P56
  symmetric P41 L19 P57
  symmetric P42 L19 P54
  coincident L15 P68
  symmetric P39 L22 P69
  symmetric L22 P68 P70
  dimension "d138" distance P39 P40 = 4
  dimension "d139" distance P39 P42 = 10
  dimension "d140" = -3
extrude "Extrude8" new body sketch "body" profile of L3 A2 L4 L8 A5 L9 L13 A8 L14 L18 A11 L19 L23 L27 L29 L35 L39 L40 L41 L42 A13 A14 A15 A16 along normal blind 15 and against normal blind 9
sketch "Sketch12" plane through (0, 0, -9) normal (0, 0, -1) x axis (1, 0, 0)
  line L1 (-163.6, 130.75) -> (-250.4, 130.75)
  line L2 (-155.5, 35.85) -> (-155.5, 122.65)
  line L3 (-250.4, 27.75) -> (-163.6, 27.75)
  line L4 (-258.5, 122.65) -> (-258.5, 35.85)
  line L5 (-154.5, 122.65) -> (-154.5, 35.85)
  line L6 (-250.4, 131.75) -> (-163.6, 131.75)
  line L7 (-259.5, 35.85) -> (-259.5, 122.65)
  line L8 (-163.6, 26.75) -> (-250.4, 26.75)
  line L9 (-203.5218, 30.1221) -> (-210.4782, 30.1221)
  line L10 (-203.5218, 27.75) -> (-203.5218, 30.1221)
  line L11 (-210.4782, 27.75) -> (-203.5218, 27.75)
  line L12 (-210.4782, 30.1221) -> (-210.4782, 27.75)
  line L13 (-210.4782, 28) -> (-210.4782, 27.75)
  line L14 (-210.4782, 27.75) -> (-209.6476, 30.1221)
  line L15 (-207, 30.1221) -> (-207, 27.75)
  line L16 (-203.5218, 27.75) -> (-204.3524, 30.1221)
  line L17 (-250.4, 30.75) -> (-163.6, 30.75)
  line L18 (-158.5, 35.85) -> (-158.5, 122.65)
  line L19 (-163.6, 127.75) -> (-250.4, 127.75)
  line L20 (-255.5, 122.65) -> (-255.5, 35.85)
  arc A1 centre (-163.6, 122.65) radius 8.1 clockwise from (-163.6, 130.75) to (-155.5, 122.65)
  arc A2 centre (-163.6, 35.85) radius 8.1 clockwise from (-155.5, 35.85) to (-163.6, 27.75)
  arc A3 centre (-250.4, 35.85) radius 8.1 clockwise from (-250.4, 27.75) to (-258.5, 35.85)
  arc A4 centre (-250.4, 122.65) radius 8.1 clockwise from (-258.5, 122.65) to (-250.4, 130.75)
  arc A5 centre (-163.6, 35.85) radius 9.1 clockwise from (-154.5, 35.85) to (-163.6, 26.75)
  arc A6 centre (-163.6, 122.65) radius 9.1 clockwise from (-163.6, 131.75) to (-154.5, 122.65)
  arc A7 centre (-250.4, 122.65) radius 9.1 clockwise from (-259.5, 122.65) to (-250.4, 131.75)
  arc A8 centre (-250.4, 35.85) radius 9.1 clockwise from (-250.4, 26.75) to (-259.5, 35.85)
  arc A9 centre (-250.4, 35.85) radius 5.1 clockwise from (-250.4, 30.75) to (-255.5, 35.85)
  arc A10 centre (-163.6, 35.85) radius 5.1 clockwise from (-158.5, 35.85) to (-163.6, 30.75)
  arc A11 centre (-163.6, 122.65) radius 5.1 clockwise from (-163.6, 127.75) to (-158.5, 122.65)
  arc A12 centre (-250.4, 122.65) radius 5.1 clockwise from (-255.5, 122.65) to (-250.4, 127.75)
  point P26 (-210.4782, 28)
  point P27 (-209.6476, 30.1221)
  point P28 (-207, 27.75)
  point P29 (-207, 30.1221)
  point P25 (-210.4782, 27.75)
  point P31 (-203.5218, 27.75)
  point P30 (-204.3524, 30.1221)
  horizontal L9
  vertical L10
  horizontal L11
  vertical L12
  midpoint L3 L11
  coincident L12 P26
  perpendicular L11 L13
  coincident L9 P27
  midpoint L11 P28
  midpoint L9 P29
  symmetric P25 L15 P31
  symmetric P27 L15 P30
  dimension "d152" = 3
extrude "Extrude9" new body sketch "Sketch12" profile of L3 L9 L11 L14 L16 against normal blind 2
extrude "Extrude10" new body sketch "Sketch12" profile of L1 A1 L2 A2 L3 A3 L4 A4 A5 L5 A6 L6 A7 L7 A8 L8 L9 L10 L11 L12 L13 L14 L16 along normal blind 6
extrude "Extrude11" add sketch "Sketch12" profile of L1 A1 L2 A2 L3 A3 L4 A4 L9 L10 L11 L12 L13 L14 L16 L20 A9 A10 L17 L19 L18 A11 A12 against normal blind 3
extrude "Extrude12" new body sketch "Sketch12" profile of L3 L9 L11 L14 L16 against normal blind 2
combine "Combine1"
combine "Combine2"
fillet "Fillet3" radius 5
sketch "flatdxfforpcb" plane through (0, 0, 1.6) normal (0, 0, 1) x axis (-1, 0, 0)
  line L1 (157.1, 69.25) -> (157.1, 89.25)
  line L2 (155.91, 69.25) -> (157.1, 69.25)
  line L3 (155.5, 35.85) -> (155.5, 68.84)
  line L4 (196.59, 27.75) -> (163.6, 27.75)
  line L5 (197, 29.35) -> (197, 28.16)
  line L6 (217, 29.35) -> (197, 29.35)
  line L7 (217, 28.16) -> (217, 29.35)
  line L8 (250.4, 27.75) -> (217.41, 27.75)
  line L9 (258.5, 68.84) -> (258.5, 35.85)
  line L10 (256.9, 69.25) -> (258.09, 69.25)
  line L11 (256.9, 89.25) -> (256.9, 69.25)
  line L12 (258.09, 89.25) -> (256.9, 89.25)
  line L13 (258.5, 122.65) -> (258.5, 89.66)
  line L14 (217.41, 130.75) -> (250.4, 130.75)
  line L15 (217, 129.15) -> (217, 130.34)
  line L16 (197, 129.15) -> (217, 129.15)
  line L17 (197, 130.34) -> (197, 129.15)
  line L18 (163.6, 130.75) -> (196.59, 130.75)
  line L19 (155.5, 89.66) -> (155.5, 122.65)
  line L20 (157.1, 89.25) -> (155.91, 89.25)
  arc A1 centre (155.91, 68.84) radius 0.41 clockwise from (155.5, 68.84) to (155.91, 69.25)
  arc A2 centre (163.6, 35.85) radius 8.1 clockwise from (163.6, 27.75) to (155.5, 35.85)
  arc A3 centre (196.59, 28.16) radius 0.41 clockwise from (197, 28.16) to (196.59, 27.75)
  arc A4 centre (217.41, 28.16) radius 0.41 clockwise from (217.41, 27.75) to (217, 28.16)
  arc A5 centre (250.4, 35.85) radius 8.1 clockwise from (258.5, 35.85) to (250.4, 27.75)
  arc A6 centre (258.09, 68.84) radius 0.41 clockwise from (258.09, 69.25) to (258.5, 68.84)
  arc A7 centre (258.09, 89.66) radius 0.41 clockwise from (258.5, 89.66) to (258.09, 89.25)
  arc A8 centre (250.4, 122.65) radius 8.1 clockwise from (250.4, 130.75) to (258.5, 122.65)
  arc A9 centre (217.41, 130.34) radius 0.41 clockwise from (217, 130.34) to (217.41, 130.75)
  arc A10 centre (196.59, 130.34) radius 0.41 clockwise from (196.59, 130.75) to (197, 130.34)
  arc A11 centre (163.6, 122.65) radius 8.1 clockwise from (155.5, 122.65) to (163.6, 130.75)
  arc A12 centre (155.91, 89.66) radius 0.41 clockwise from (155.91, 89.25) to (155.5, 89.66)
sketch "perpforpcb" plane through (0, -27.75, 0) normal (0, 1, 0) x axis (-1, 0, 0)
  line L1 (211.23, 3.24) -> (211.23, -1.64)
  line L2 (212.93, -1.64) -> (212.93, 3.24)
  line L3 (201.07, 3.24) -> (201.07, -1.64)
  line L4 (202.77, -1.64) -> (202.77, 3.24)
  line L5 (208.69, 3.24) -> (208.69, -1.64)
  line L6 (210.39, -1.64) -> (210.39, 3.24)
  line L7 (203.61, 3.24) -> (203.61, -1.64)
  line L8 (205.31, -1.64) -> (205.31, 3.24)
  line L9 (206.15, 3.24) -> (206.15, -1.64)
  line L10 (207.85, -1.64) -> (207.85, 3.24)
  line L11 (196, 5.8) -> (218, 5.8)
  line L12 (193, 1.8) -> (193, 2.8)
  line L13 (197.2, 1.8) -> (193, 1.8)
  line L14 (197.2, -0.2) -> (197.2, 1.8)
  line L15 (193, -0.2) -> (197.2, -0.2)
  line L16 (193, -1.2) -> (193, -0.2)
  line L17 (218, -4.2) -> (196, -4.2)
  line L18 (221, -0.2) -> (221, -1.2)
  line L19 (216.8, -0.2) -> (221, -0.2)
  line L20 (216.8, 1.8) -> (216.8, -0.2)
  line L21 (221, 1.8) -> (216.8, 1.8)
  line L22 (221, 2.8) -> (221, 1.8)
  line L23 (202.77, 3.24) -> (202.77, -1.64)
  line L24 (201.07, -1.64) -> (201.07, 3.24)
  line L25 (205.31, 3.24) -> (205.31, -1.64)
  line L26 (203.61, -1.64) -> (203.61, 3.24)
  line L27 (207.85, 3.24) -> (207.85, -1.64)
  line L28 (206.15, -1.64) -> (206.15, 3.24)
  line L29 (210.39, 3.24) -> (210.39, -1.64)
  line L30 (208.69, -1.64) -> (208.69, 3.24)
  line L31 (212.93, 3.24) -> (212.93, -1.64)
  line L32 (211.23, -1.64) -> (211.23, 3.24)
  line L33 (196.59, 0) -> (163.6, 0)
  line L34 (196.59, 1.6) -> (196.59, 0)
  line L35 (163.6, 1.6) -> (196.59, 1.6)
  line L36 (163.6, 0) -> (163.6, 1.6)
  arc A1 centre (212.08, -1.64) radius 0.85 clockwise from (212.93, -1.64) to (211.23, -1.64)
  arc A2 centre (212.08, 3.24) radius 0.85 clockwise from (211.23, 3.24) to (212.93, 3.24)
  arc A3 centre (201.92, -1.64) radius 0.85 clockwise from (202.77, -1.64) to (201.07, -1.64)
  arc A4 centre (201.92, 3.24) radius 0.85 clockwise from (201.07, 3.24) to (202.77, 3.24)
  arc A5 centre (209.54, -1.64) radius 0.85 clockwise from (210.39, -1.64) to (208.69, -1.64)
  arc A6 centre (209.54, 3.24) radius 0.85 clockwise from (208.69, 3.24) to (210.39, 3.24)
  arc A7 centre (204.46, -1.64) radius 0.85 clockwise from (205.31, -1.64) to (203.61, -1.64)
  arc A8 centre (204.46, 3.24) radius 0.85 clockwise from (203.61, 3.24) to (205.31, 3.24)
  arc A9 centre (207, -1.64) radius 0.85 clockwise from (207.85, -1.64) to (206.15, -1.64)
  arc A10 centre (207, 3.24) radius 0.85 clockwise from (206.15, 3.24) to (207.85, 3.24)
  arc A11 centre (218, 2.8) radius 3 clockwise from (218, 5.8) to (221, 2.8)
  arc A12 centre (196, 2.8) radius 3 clockwise from (193, 2.8) to (196, 5.8)
  arc A13 centre (196, -1.2) radius 3 clockwise from (196, -4.2) to (193, -1.2)
  arc A14 centre (218, -1.2) radius 3 clockwise from (221, -1.2) to (218, -4.2)
  circle C1 centre (201.92, 0.8) radius 0.5
  arc A15 centre (201.92, 3.24) radius 0.85 clockwise from (201.07, 3.24) to (202.77, 3.24)
  arc A16 centre (201.92, -1.64) radius 0.85 clockwise from (202.77, -1.64) to (201.07, -1.64)
  circle C2 centre (204.46, 0.8) radius 0.5
  arc A17 centre (204.46, 3.24) radius 0.85 clockwise from (203.61, 3.24) to (205.31, 3.24)
  arc A18 centre (204.46, -1.64) radius 0.85 clockwise from (205.31, -1.64) to (203.61, -1.64)
  circle C3 centre (207, 0.8) radius 0.5
  arc A19 centre (207, 3.24) radius 0.85 clockwise from (206.15, 3.24) to (207.85, 3.24)
  arc A20 centre (207, -1.64) radius 0.85 clockwise from (207.85, -1.64) to (206.15, -1.64)
  circle C4 centre (209.54, 0.8) radius 0.5
  arc A21 centre (209.54, 3.24) radius 0.85 clockwise from (208.69, 3.24) to (210.39, 3.24)
  arc A22 centre (209.54, -1.64) radius 0.85 clockwise from (210.39, -1.64) to (208.69, -1.64)
  circle C5 centre (212.08, 0.8) radius 0.5
  arc A23 centre (212.08, 3.24) radius 0.85 clockwise from (211.23, 3.24) to (212.93, 3.24)
  arc A24 centre (212.08, -1.64) radius 0.85 clockwise from (212.93, -1.64) to (211.23, -1.64)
